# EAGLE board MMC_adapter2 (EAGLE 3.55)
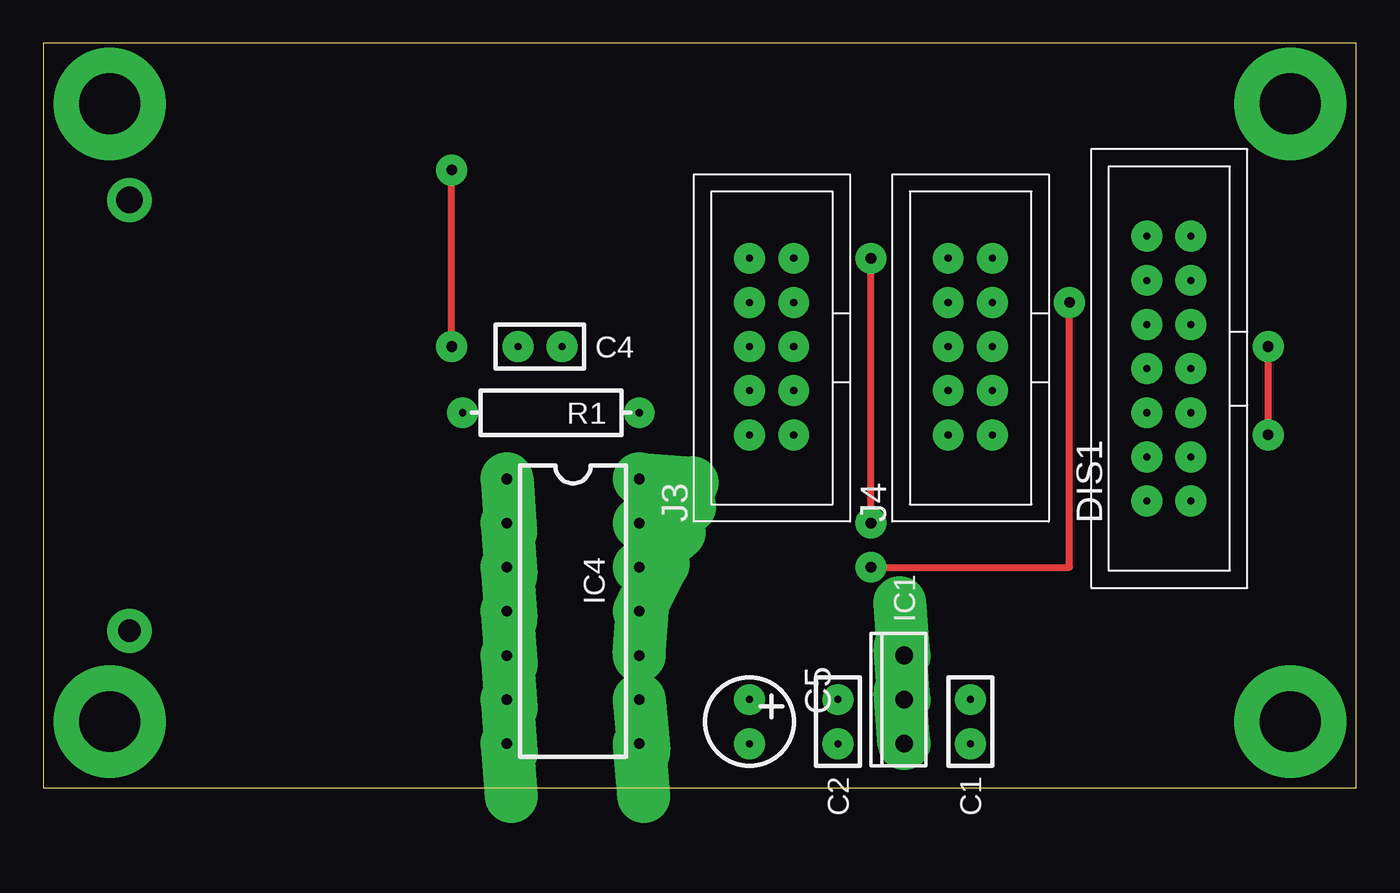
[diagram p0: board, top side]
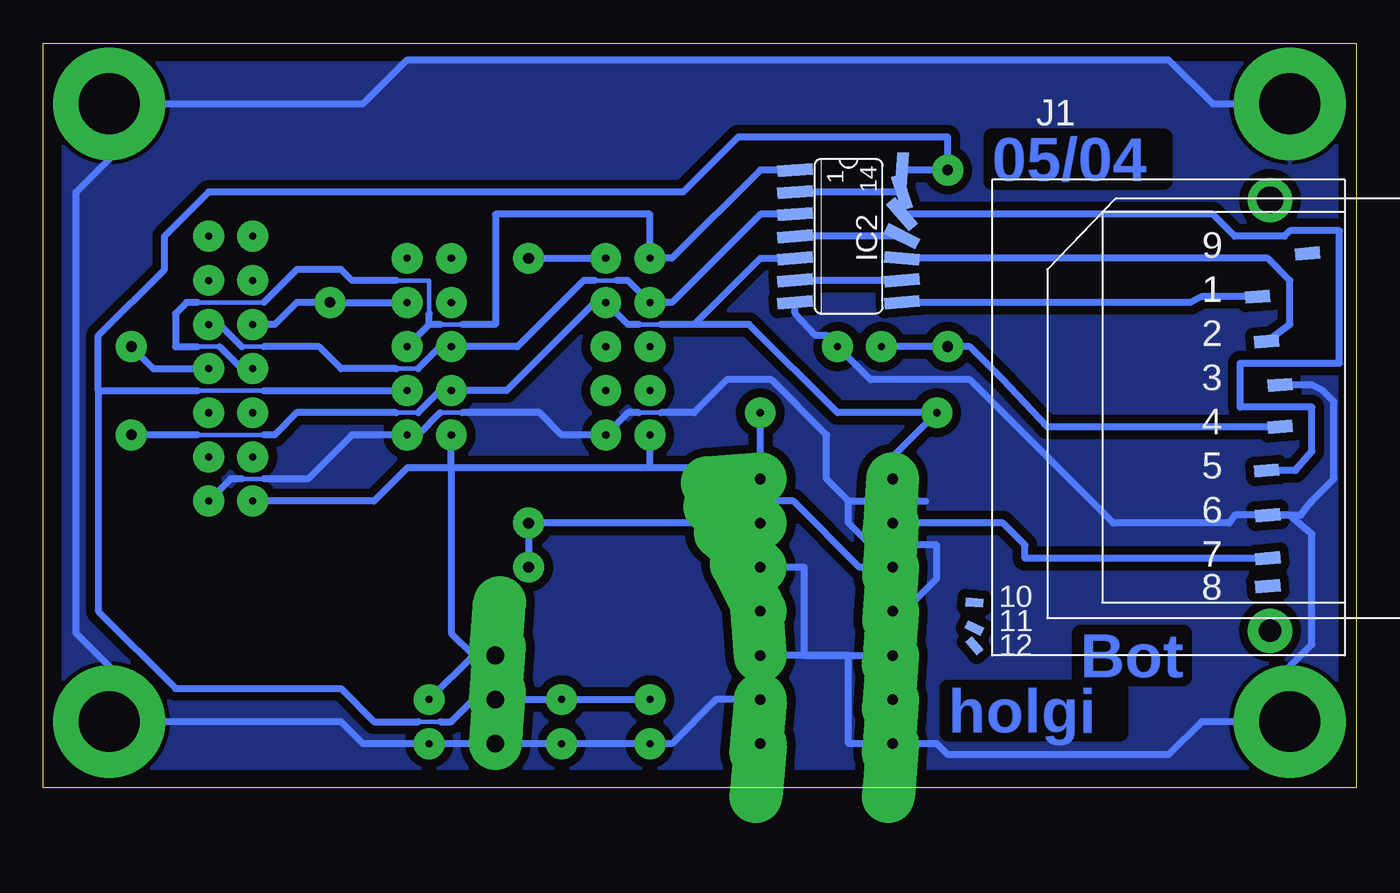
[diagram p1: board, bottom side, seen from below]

Size 75.55 x 42.85 mm. Coordinates in mm from the lower left corner, seen from the top.
Outline: 0,0 75.55,0 75.55,42.85 0,42.85 0,0
Copper layers used: Top, Bottom

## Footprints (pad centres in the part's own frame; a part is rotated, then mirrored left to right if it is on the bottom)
RM2,5 = drill 0.406 pad 1.778 round:  -1.27,0;  1.27,0
KO01 = drill 0.406 pad 1.778 round:  -1.27,0;  1.27,0
7 = drill 0.406 pad 1.778 round:  0,0;  2.54,0;  5.08,0;  7.62,0;  10.16,0;  10.16,2.54;  7.62,2.54;  5.08,2.54;  2.54,2.54;  0,2.54;  12.7,0;  12.7,2.54;  15.24,0;  15.24,2.54
220A = drill 1.016 pad 3.048 offset:  -2.54,0;  0,0;  2.54,0
14 = smd 0.66 x 2.032 rotated 4.3:  -3.81,-3.073;  1.27,3.073 | smd 0.66 x 2.032 rotated 94.3:  -3.81,3.073 | smd 0.66 x 2.032 rotated 4.4:  -2.54,-3.073 | smd 0.66 x 2.032 rotated 4.5:  -1.27,-3.073 | smd 0.66 x 2.032 rotated 71.8:  -2.54,3.073 | smd 0.66 x 2.032 rotated 49.3:  -1.27,3.073 | smd 0.66 x 2.032 rotated 4.6:  0,-3.073 | smd 0.66 x 2.032 rotated 26.8:  0,3.073 | smd 0.66 x 2.032 rotated 4.7:  1.27,-3.073;  2.54,-3.073 | smd 0.66 x 2.032 rotated 5:  2.54,3.073 | smd 0.66 x 2.032 rotated 4.8:  3.81,-3.073 | smd 0.66 x 2.032 rotated 4.9:  3.81,3.073
L-14B = drill 0.61 pad 3.048 offset:  -7.62,-3.81;  -5.08,-3.81;  -2.54,-3.81;  0,-3.81;  2.54,-3.81;  5.08,-3.81;  7.62,-3.81;  7.62,3.81;  5.08,3.81;  2.54,3.81;  0,3.81;  -2.54,3.81;  -5.08,3.81;  -7.62,3.81
C_SOCK = smd 1.422 x 0.711 rotated 4.3:  15.291,20.65 | smd 1.422 x 0.711 rotated 4.4:  15.799,18.085 | smd 1.422 x 0.711 rotated 4.5:  16.586,15.57 | smd 1.422 x 0.711 rotated 4.7:  15.799,10.643;  15.875,8.077 | smd 1.422 x 0.711 rotated 4.8:  15.875,5.588 | smd 1.422 x 0.711 rotated 4.9:  15.875,3.988 | smd 1.422 x 0.711 rotated 4.6:  16.586,13.157 | smd 1.422 x 0.711 rotated 5:  18.161,23.139 | smd 1.016 x 0.508 rotated 4.3:  -1.016,3.048 | smd 1.016 x 0.508 rotated 26.8:  -1.016,1.575 | smd 1.016 x 0.508 rotated 49.3:  -1.016,0.559 | drill 1.524 pad 2.54 round:  16.002,26.213 | drill 1.295 pad 2.54 round:  16.002,1.422
5 = drill 0.406 pad 1.778 round:  0,0;  2.54,0;  5.08,0;  7.62,0;  10.16,0;  10.16,2.54;  7.62,2.54;  5.08,2.54;  2.54,2.54;  0,2.54
S04 = drill 0.406 pad 1.778 round:  -5.08,0;  5.08,0
HRUNG = drill 3.505 pad 6.452 round:  0,0

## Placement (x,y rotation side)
C1  C100NK  [RM2,5]  53.34,3.81 270 top
C2  C100NK  [RM2,5]  45.72,3.81 270 top
C4  C100NK  [RM2,5]  28.57,25.4 0 top
C5  47u  [KO01]  40.64,3.81 270 top
DIS1  LCD_DOPPEL  [7]  66.04,16.51 90 top
IC1  LM1086_3,3  [220A]  49.53,5.08 90 top
IC2  74LVX04  [14]  29.21,31.75 270 bottom
IC4  74HCT125  [L-14B]  30.48,10.16 270 top
J1  MMC_SOCK  [C_SOCK]  20.95,7.62 0 bottom
J3  8BITPORT  [5]  43.18,20.32 90 top
J4  8BITPORT  [5]  54.61,20.32 90 top
R1  10k  [S04]  29.21,21.59 180 top
U$18  BOHRUNG  [HRUNG]  3.81,39.37 0 top
U$19  BOHRUNG  [HRUNG]  71.75,39.37 0 top
U$20  BOHRUNG  [HRUNG]  71.75,3.81 0 top
U$21  BOHRUNG  [HRUNG]  3.81,3.81 0 top

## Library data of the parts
C1 C2 C4 C5 DIS1 IC1 IC4 J3 J4 R1 = holg_plt
IC2 = 74XXSMD
J1 = ic_holg
U$18-U$21 = holgnorm

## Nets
+3V: C2. C4. C5. IC1. IC2. J1. J4.
+5V: C1. DIS1. IC1. IC4. J3. J4. R1.
/CS: DIS1. IC2. IC4. J3. J4. R1.
GND: C1. C2. C4. C5. DIS1. IC1. IC2. IC4. J1. J3. J4. U$18. U$19. U$20. U$21.
MISO: DIS1. IC4. J3. J4.
MOSI: DIS1. IC2. J3. J4.
N$1: IC2.
N$2: IC2.
N$3: IC2.
N$5: IC4. J1.
N$6: IC2. J1.
N$7: IC2. J1.
N$8: IC2. J1.
SCK: DIS1. IC2. J3. J4.

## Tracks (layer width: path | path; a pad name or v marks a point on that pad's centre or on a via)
+3V  (via drill 0.61 pad 1.78)
  Top 0.406: v23.5,25.4 v23.5,35.56
  Bottom 0.254: 53.98,3.81 52.7,3.81 | 66.67,22.86 62.87,22.86
  Bottom 0.406: 40.64,5.08 45.72,5.08 49.53,5.08 50.8,5.08 52.07,3.81 52.7,3.81 | 26.14,35.56 v23.5,35.56 23.5,37.47 35.56,37.47 38.73,34.29 66.04,34.29 68.58,31.75 68.58,29.84 72.39,26.04 72.39,22.86 | 72.39,22.86 72.39,10.16 67.94,5.71 58.42,5.71 56.52,3.81 53.98,3.81 | 4.37,20.78 17.78,20.78 20.32,23.5 22.23,25.4 v23.5,25.4 27.3,25.4 | 62.87,22.86 54.61,22.86 | 72.39,22.86 66.67,22.86
+5V
  Bottom 0.406: 50.8,7.62 53.34,5.08 | 50.8,7.62 IC1. | 52.07,18.41 52.07,8.89 50.8,7.62 | 52.07,18.41 J4. | 40.64,18.41 J3. | 40.64,18.41 52.07,18.41 | 40.64,18.41 38.1,18.41 37.47,17.78 IC4. 34.29,21.59 | 52.07,18.41 54.61,18.41 56.52,16.51 63.5,16.51
/CS  (via drill 0.61 pad 1.78)
  Top 0.406: v70.48,20.32 v70.48,25.4
  Bottom 0.254: 40.01,26.67 41.27,26.67 | 53.98,21.59 55.24,21.59 | 62.87,20.32 66.67,20.32
  Bottom 0.406: 41.27,26.67 41.91,26.67 43.18,27.94 43.81,27.94 48.9,22.86 52.07,22.86 52.7,22.86 53.98,21.59 | 32.28,30.48 34.29,30.48 38.1,26.67 | 38.1,26.67 40.01,26.67 | 26.67,17.78 26.67,19.05 R1. 29.84,21.59 34.92,26.67 38.1,26.67 | 55.24,21.59 60.96,21.59 62.23,20.32 62.87,20.32 | 66.04,24.13 69.22,24.13 v70.48,25.4 | 66.67,20.32 v70.48,20.32
GND
  Bottom 0.254: 40.01,21.59 41.27,21.59 | 51.44,21.59 52.7,21.59 | 62.87,17.78 64.14,17.78
  Bottom 0.406: 41.27,21.59 41.91,21.59 43.18,20.32 45.72,20.32 46.99,21.59 51.44,21.59 | U$18. 8.26,39.37 10.79,41.91 54.61,41.91 57.15,39.37 U$19. 71.75,36.2 73.66,34.29 73.66,8.89 71.75,6.99 U$20. 58.42,3.81 57.15,2.54 C1. 49.53,2.54 C2. C5. 39.37,2.54 36.83,5.08 34.29,5.08 34.29,7.62 31.75,7.62 | 5.08,15.7 3.81,15.7 2.54,14.61 2.54,8.26 3.81,6.99 U$21. 8.89,3.81 10.79,1.91 23.5,1.91 24.13,2.54 26.67,2.54 29.21,2.54 29.21,7.62 | 5.08,15.7 3.17,15.7 2.54,16.51 1.27,17.78 1.27,22.23 1.91,22.86 2.54,23.19 4.37,23.19 | 5.08,15.7 6.99,15.7 7.3,15.24 13.97,15.24 22.23,23.5 27.94,23.5 C4. 30.48,26.04 31.11,26.04 32.28,27.3 32.28,27.94 | 29.21,7.62 31.75,7.62 | 29.21,7.62 26.67,7.62 | 34.29,12.7 34.29,15.24 34.29,12.7 | 26.67,7.62 26.67,10.16 | 40.01,21.59 38.1,21.59 36.2,23.5 33.66,23.5 30.48,20.32 30.48,17.78 29.21,16.51 | 29.21,16.51 24.77,16.51 | 34.29,12.7 31.75,12.7 31.75,7.62 | 31.75,7.62 26.67,7.62 | 26.67,7.62 26.67,10.16 | 26.67,10.16 26.04,10.16 24.13,12.06 24.13,13.97 27.94,13.97 29.21,15.24 29.21,16.51 | 52.7,21.59 53.98,20.32 54.61,20.32 57.78,20.32 60.33,17.78 62.87,17.78 | 66.04,16.51 64.77,17.78 64.14,17.78
  pour Bottom (isolate 0.508): 0.64,42.55 0.64,0.64 74.93,0.64 74.93,42.55
MISO  (via drill 0.61 pad 1.78)
  Top 0.406: v59.05,27.94 59.05,12.7 v47.62,12.7 | v47.62,15.24 v47.62,30.48
  Bottom 0.406: 54.61,27.94 v59.05,27.94 60.96,27.94 62.23,26.67 63.5,26.67 | v47.62,30.48 43.18,30.48 | 26.67,12.7 28.57,12.7 32.38,16.51 36.83,16.51 38.1,15.24 v47.62,15.24 v47.62,12.7
MOSI
  Bottom 0.254: 42.55,29.21 43.81,29.21 | 62.87,25.4 64.14,25.4 | 53.98,24.13 55.24,24.13
  Bottom 0.406: 32.28,33.02 34.29,33.02 39.37,27.94 40.64,27.94 41.91,29.21 42.55,29.21 | 43.81,29.21 44.45,29.21 48.26,25.4 52.07,25.4 52.7,25.4 53.98,24.13 | 66.04,26.67 65.41,26.67 64.14,25.4 | 55.24,24.13 58.42,24.13 59.69,25.4 62.87,25.4
N$1
  Bottom 0.406: 26.14,29.21 32.28,29.21
N$2
  Bottom 0.406: 26.14,31.75 32.28,31.75
N$3
  Bottom 0.406: 26.14,34.29 32.28,34.29
N$5
  Bottom 0.406: 5.08,13.21 19.05,13.21 19.05,13.97 20.32,15.24 26.67,15.24
N$6
  Bottom 0.406: 5.16,18.26 3.49,18.26 2.54,19.37 2.54,21.91 6.67,21.91 6.67,24.45 0.95,24.45 0.95,32.07 3.81,32.07 4.13,31.75 6.99,31.75 8.26,33.02 26.14,33.02
N$7
  Bottom 0.406: 5.16,25.7 5.08,25.7 3.81,26.67 3.81,29.21 5.08,30.48 26.14,30.48
N$8
  Bottom 0.406: 5.66,28.27 8.89,28.27 9.53,27.94 IC2.
SCK
  Bottom 0.254: 51.44,26.67 52.7,26.67 | 53.34,27.3 53.34,29.21 55.24,29.21 | 66.67,25.4 65.41,25.4 | 62.87,27.94 66.67,27.94
  Bottom 0.406: 32.28,35.56 34.29,35.56 39.37,30.48 40.64,30.48 40.64,33.02 49.53,33.02 49.53,26.67 51.44,26.67 | 52.7,26.67 53.34,26.67 | 53.34,26.67 54.61,25.4 | 53.34,26.67 53.34,27.3 | 63.5,24.13 64.14,24.13 65.41,25.4 | 55.24,29.21 57.78,29.21 58.42,29.84 60.96,29.84 62.87,27.94 | 66.67,25.4 67.94,25.4 67.94,27.3 67.31,27.94 66.67,27.94

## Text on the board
Bottom: 05/04 | Bot | holgi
